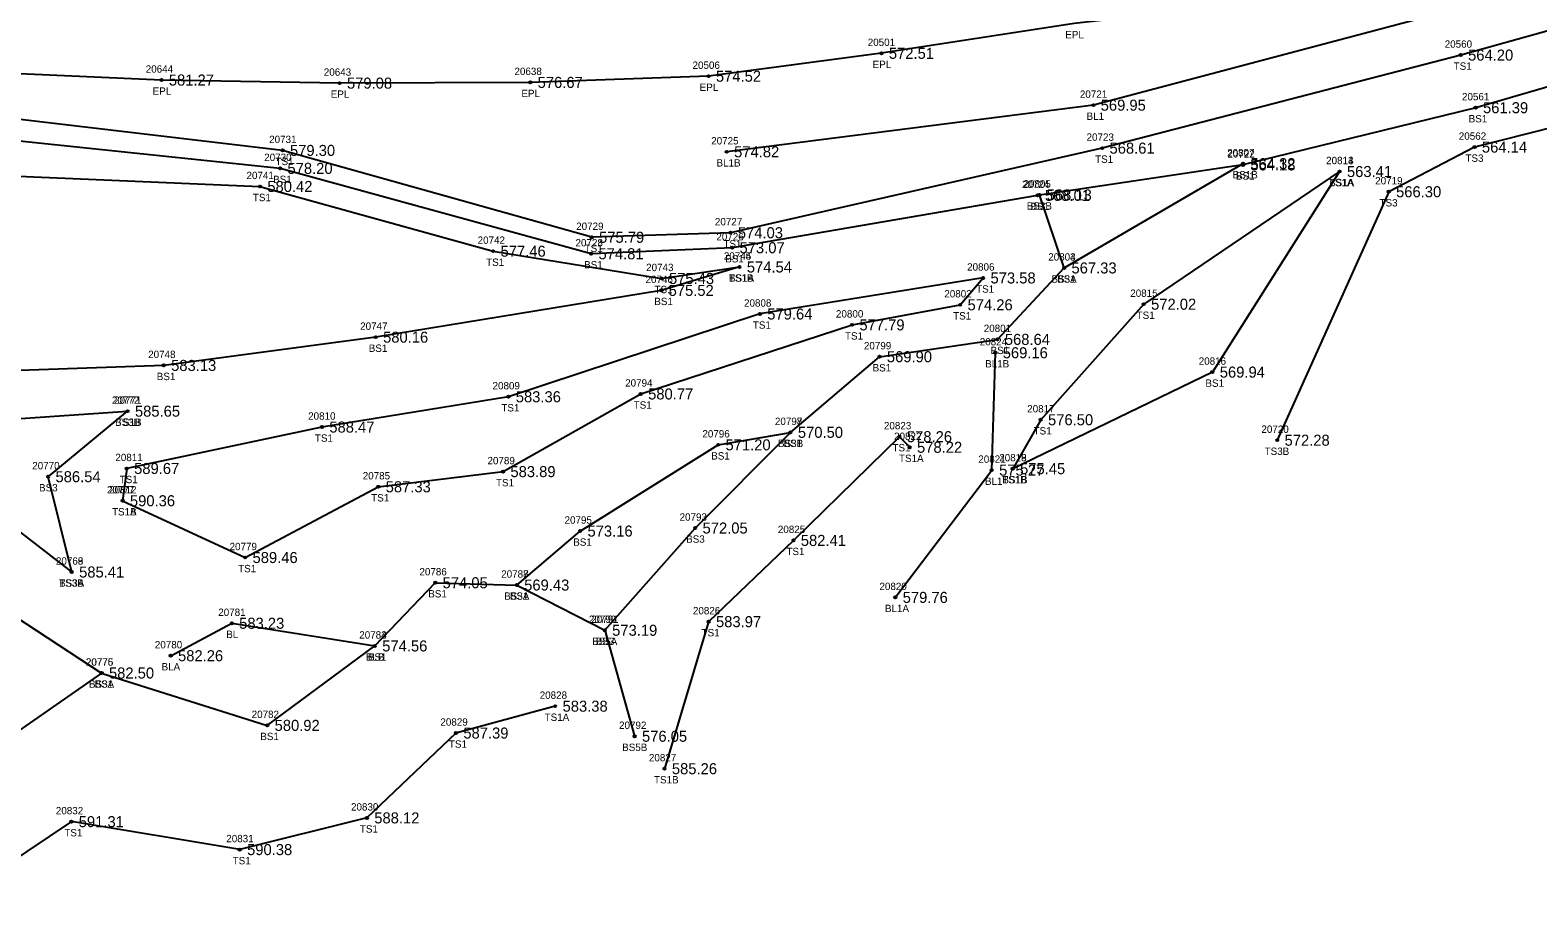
# Model space of a CAD drawing. Extents: x 1540443 to 1541844, y 887157 to 888162.
# Drawn here: x 1540572.9 to 1540777.9, y 887433.6 to 887551.3 of the extents above; entities that cross this region are included whole.
import ezdxf

# ---------------------------------------------------------------- set-up
doc = ezdxf.new("R2010")
doc.units = 0
for name, color, linetype in [('RD_DTM_BkLn1', 7, 'Continuous'), ('RD_DTM_BkLn2', 7, 'Continuous'), ('RD_DTM_BkLn_txCode', 7, 'Continuous'), ('RD_EX_Road', 7, 'Continuous'), ('RD_EX_Road_txCode', 7, 'Continuous'), ('RD_EX_TX_Misc_ELEV', 7, 'Continuous'), ('RD_EX_TX_Road_ELEV', 7, 'Continuous'), ('RD_SMD_Locator', 7, 'Continuous')]:
    doc.layers.add(name, color=color, linetype=linetype)

msp = doc.modelspace()

# ---------------------------------------------------------------- linework, layer by layer
at = {"layer": 'RD_DTM_BkLn1'}
for points in [[(1540954.63, 887607.67), (1540911.91, 887595.52), (1540863.1, 887582.06), (1540814.48, 887567.51), (1540766.41, 887554.06), (1540717.46, 887541.1), (1540667.62, 887534.76)], [(1540690.54, 887474.18), (1540703.65, 887491.48), (1540704.14, 887507.44)], [(1540592.02, 887466.25), (1540600.33, 887470.66), (1540619.78, 887467.58)]]:
    msp.add_lwpolyline(points, dxfattribs=at)
at = {"layer": 'RD_DTM_BkLn2'}
for p, q in [((1540713.49, 887518.97), (1540710.12, 887528.9)), ((1540553.06, 887497.25), (1540578.57, 887477.63)), ((1540651.04, 887469.71), (1540655.1, 887455.3)), ((1540582.63, 887463.9), (1540559.13, 887447.58))]:
    msp.add_line(p, q, dxfattribs=at)
for points in [[(1540960.58, 887575.27), (1540958.57, 887598.03), (1540949.34, 887601.53), (1540912.42, 887588.35), (1540865.58, 887574.46), (1540822.62, 887563.37), (1540767.41, 887547.91), (1540718.66, 887535.26), (1540668.13, 887523.76), (1540649.26, 887523.14), (1540607.24, 887534.95), (1540564.64, 887539.95), (1540513.61, 887544.12), (1540463.72, 887552.73)], [(1540960.58, 887575.27), (1540955.45, 887594.2), (1540950.03, 887596.51), (1540913.42, 887584.06), (1540866.75, 887567.94), (1540825.46, 887557.08), (1540769.44, 887540.76), (1540737.8, 887532.98), (1540709.87, 887528.84), (1540668.36, 887521.72), (1540649.18, 887520.9), (1540606.9, 887532.51), (1540564.07, 887536.98), (1540513.03, 887541.52), (1540462.71, 887549.66)], [(1540900.6, 887567.53), (1540867.5, 887560.94), (1540827.24, 887552.46), (1540817.08, 887547.51), (1540769.29, 887535.4), (1540757.62, 887529.33), (1540742.46, 887495.55)], [(1540461.05, 887539.25), (1540511.05, 887534.75), (1540564.9, 887531.71), (1540604.16, 887530.05), (1540635.87, 887521.25), (1540658.77, 887517.54), (1540669.35, 887519.1)], [(1540457.25, 887532.15), (1540491.31, 887510.51), (1540538.24, 887496.06), (1540547.91, 887492.89), (1540564.9, 887475.48), (1540582.63, 887463.9), (1540605.15, 887456.78), (1540619.78, 887467.58), (1540627.99, 887476.17), (1540639.08, 887475.86), (1540647.69, 887483.2), (1540666.45, 887494.92), (1540676.29, 887496.62), (1540688.39, 887506.9), (1540704.43, 887509.26), (1540713.49, 887518.97), (1540737.81, 887533.15)], [(1540457.25, 887532.15), (1540498.35, 887514), (1540541.32, 887498.88), (1540553.06, 887497.25), (1540586.16, 887499.5)], [(1540750.94, 887532.08), (1540733.65, 887504.81), (1540706.5, 887491.68)], [(1540750.94, 887532.08), (1540724.31, 887514.04), (1540710.3, 887498.33), (1540706.5, 887491.68)], [(1540669.35, 887519.1), (1540658.72, 887515.92), (1540619.9, 887509.56), (1540591.08, 887505.72), (1540555.73, 887504.5), (1540519.67, 887515.23), (1540490.26, 887524.32)], [(1540585.48, 887487.32), (1540602.15, 887479.6), (1540620.25, 887489.22), (1540637.21, 887491.28), (1540655.93, 887501.84), (1540684.66, 887511.23), (1540699.36, 887513.96), (1540702.48, 887517.61), (1540672.13, 887512.71), (1540637.94, 887501.46), (1540612.59, 887497.34), (1540586.05, 887491.71), (1540585.48, 887487.32)], [(1540578.57, 887477.63), (1540575.36, 887490.59), (1540586.16, 887499.5)], [(1540639.08, 887475.86), (1540651.04, 887469.71), (1540663.33, 887483.61), (1540676.29, 887496.62)], [(1540692.49, 887494.59), (1540691.11, 887496.03), (1540676.69, 887481.93), (1540665.16, 887470.88), (1540659.16, 887450.89)], [(1540644.3, 887459.39), (1540630.81, 887455.74), (1540618.7, 887444.2), (1540601.41, 887439.89), (1540578.52, 887443.69), (1540563.45, 887433.6)]]:
    msp.add_lwpolyline(points, dxfattribs=at)
at = {"layer": 'RD_EX_Road'}
msp.add_lwpolyline([(1541128.99, 887664.81), (1541102.04, 887656.79), (1541055.37, 887642.78), (1541004.6, 887628.06), (1540958.93, 887614.62), (1540910.77, 887599.96), (1540863.12, 887586.35), (1540837, 887578.35), (1540814.37, 887572.63), (1540785.6, 887565.57), (1540765.56, 887561), (1540743.15, 887555.32), (1540714.84, 887552.19), (1540688.66, 887548.15), (1540665.15, 887545.04), (1540640.91, 887544.2), (1540614.99, 887544.1), (1540590.77, 887544.52), (1540565.35, 887545.64), (1540542.9, 887547.56), (1540513.68, 887550.75), (1540490.5, 887554.02), (1540464.65, 887559.04)], dxfattribs=at)
at = {"layer": 'RD_SMD_Locator'}
for centre in [(1540688.66, 887548.15), (1540767.41, 887547.91), (1540665.15, 887545.04), (1540590.77, 887544.52), (1540614.99, 887544.1), (1540640.91, 887544.2), (1540717.46, 887541.1), (1540769.44, 887540.76), (1540607.24, 887534.95), (1540667.62, 887534.76), (1540718.66, 887535.26), (1540769.29, 887535.4), (1540737.8, 887532.98), (1540737.81, 887533.15), (1540606.9, 887532.51), (1540750.94, 887532.08), (1540750.94, 887532.08), (1540604.16, 887530.05), (1540709.87, 887528.84), (1540710.12, 887528.9), (1540757.62, 887529.33), (1540649.26, 887523.14), (1540668.13, 887523.76), (1540635.87, 887521.25), (1540649.18, 887520.9), (1540668.36, 887521.72), (1540669.35, 887519.1), (1540669.35, 887519.1), (1540713.49, 887518.97), (1540713.49, 887518.97), (1540658.77, 887517.54), (1540702.48, 887517.61), (1540658.72, 887515.92), (1540672.13, 887512.71), (1540699.36, 887513.96), (1540724.31, 887514.04), (1540684.66, 887511.23), (1540619.9, 887509.56), (1540704.43, 887509.26), (1540688.39, 887506.9), (1540704.14, 887507.44), (1540591.08, 887505.72), (1540733.65, 887504.81), (1540655.93, 887501.84), (1540637.94, 887501.46), (1540586.16, 887499.5), (1540586.16, 887499.5), (1540710.3, 887498.33), (1540612.59, 887497.34), (1540676.29, 887496.62), (1540676.29, 887496.62), (1540691.11, 887496.03), (1540666.45, 887494.92), (1540692.49, 887494.59), (1540742.46, 887495.55), (1540586.05, 887491.71), (1540706.5, 887491.68), (1540706.5, 887491.68), (1540575.36, 887490.59), (1540637.21, 887491.28), (1540703.65, 887491.48), (1540620.25, 887489.22), (1540585.48, 887487.32), (1540585.48, 887487.32), (1540663.33, 887483.61), (1540647.69, 887483.2), (1540676.69, 887481.93), (1540602.15, 887479.6), (1540578.57, 887477.63), (1540578.57, 887477.63), (1540627.99, 887476.17), (1540639.08, 887475.86), (1540639.08, 887475.86), (1540690.54, 887474.18), (1540600.33, 887470.66), (1540651.04, 887469.71), (1540651.04, 887469.71), (1540665.16, 887470.88), (1540619.78, 887467.58), (1540619.78, 887467.58), (1540592.02, 887466.25), (1540582.63, 887463.9), (1540582.63, 887463.9), (1540644.3, 887459.39), (1540605.15, 887456.78), (1540630.81, 887455.74), (1540655.1, 887455.3), (1540659.16, 887450.89), (1540578.52, 887443.69), (1540618.7, 887444.2), (1540601.41, 887439.89)]:
    msp.add_circle(centre, 0.15, dxfattribs=at)

# ---------------------------------------------------------------- texts
at = {"layer": 'RD_DTM_BkLn_txCode'}
for s, p in [('20560', (1540765.23, 887548.91)), ('TS1', (1540766.45, 887545.91)), ('20721', (1540715.63, 887542.1)), ('20561', (1540767.58, 887541.76)), ('BL1', (1540716.54, 887539.1)), ('BS1', (1540768.49, 887538.76)), ('20731', (1540605.41, 887535.95)), ('20725', (1540665.51, 887535.76)), ('20723', (1540716.54, 887536.26)), ('20562', (1540767.15, 887536.4)), ('20807', (1540735.65, 887534.15)), ('20722', (1540735.68, 887533.98)), ('20730', (1540604.74, 887533.51)), ('TS1', (1540606.28, 887532.95)), ('BL1B', (1540666.23, 887532.76)), ('TS1', (1540717.7, 887533.26)), ('20813', (1540749.11, 887533.08)), ('20814', (1540749.11, 887533.08)), ('TS3', (1540768.05, 887533.4)), ('20741', (1540602.33, 887531.05)), ('BS1', (1540605.95, 887530.51)), ('20724', (1540707.76, 887529.84)), ('20805', (1540707.96, 887529.9)), ('BS1B', (1540736.39, 887531.15)), ('BS1', (1540736.85, 887530.98)), ('TS1A', (1540749.49, 887530.08)), ('BS1A', (1540749.51, 887530.08)), ('20719', (1540755.78, 887530.33)), ('TS1', (1540603.2, 887528.05)), ('BS3B', (1540708.41, 887526.9)), ('BS1', (1540708.93, 887526.84)), ('TS3', (1540756.37, 887527.33)), ('20729', (1540647.15, 887524.14)), ('20727', (1540666.01, 887524.76)), ('20742', (1540633.75, 887522.25)), ('20728', (1540647.06, 887521.9)), ('20726', (1540666.21, 887522.72)), ('TS1', (1540667.17, 887521.76)), ('TS1', (1540648.3, 887521.14)), ('20744', (1540667.23, 887520.1)), ('20745', (1540667.23, 887520.1)), ('BS1', (1540667.41, 887519.72)), ('20803', (1540711.33, 887519.97)), ('20804', (1540711.33, 887519.97)), ('TS1', (1540634.91, 887519.25)), ('BS1', (1540648.23, 887518.9)), ('20743', (1540656.66, 887518.54)), ('20806', (1540700.3, 887518.61)), ('20746', (1540656.58, 887516.92)), ('TS1', (1540657.81, 887515.54)), ('TS1B', (1540667.92, 887517.1)), ('BS1A', (1540667.92, 887517.1)), ('TS1', (1540701.52, 887515.61)), ('BS3A', (1540711.77, 887516.97)), ('BS1', (1540712.54, 887516.97)), ('BS1', (1540657.77, 887513.92)), ('20808', (1540669.97, 887513.71)), ('20802', (1540697.2, 887514.96)), ('20815', (1540722.48, 887515.04)), ('20800', (1540682.47, 887512.23)), ('TS1', (1540698.4, 887511.96)), ('TS1', (1540723.35, 887512.04)), ('20747', (1540617.78, 887510.56)), ('TS1', (1540671.17, 887510.71)), ('TS1', (1540683.7, 887509.23)), ('20801', (1540702.56, 887510.26)), ('BS1', (1540618.95, 887507.56)), ('20799', (1540686.27, 887507.9)), ('20824', (1540702.02, 887508.44)), ('BS1', (1540703.49, 887507.26)), ('20748', (1540588.96, 887506.72)), ('BL1B', (1540702.75, 887505.44)), ('20816', (1540731.79, 887505.81)), ('BS1', (1540590.13, 887503.72)), ('BS1', (1540687.45, 887504.9)), ('20809', (1540635.78, 887502.46)), ('20794', (1540653.81, 887502.84)), ('BS1', (1540732.7, 887502.81)), ('20772', (1540584.04, 887500.5)), ('20771', (1540584.32, 887500.5)), ('TS1', (1540636.98, 887499.46)), ('TS1', (1540654.97, 887499.84)), ('20817', (1540708.47, 887499.33)), ('BS3B', (1540584.46, 887497.5)), ('TS1B', (1540584.72, 887497.5)), ('20810', (1540610.71, 887498.34)), ('20797', (1540674.17, 887497.62)), ('20798', (1540674.17, 887497.62)), ('20823', (1540688.99, 887497.03)), ('TS1', (1540611.63, 887495.34)), ('20796', (1540664.31, 887495.92)), ('20822', (1540690.37, 887495.59)), ('TS1', (1540709.34, 887496.33)), ('20720', (1540740.31, 887496.55)), ('BS1', (1540665.51, 887492.92)), ('BS3B', (1540674.59, 887494.62)), ('BS1', (1540675.34, 887494.62)), ('TS1', (1540690.15, 887494.03)), ('TS3B', (1540740.75, 887493.55)), ('20770', (1540573.2, 887491.59)), ('20811', (1540584.5, 887492.71)), ('20789', (1540635.09, 887492.28)), ('TS1A', (1540691.04, 887492.59)), ('20821', (1540701.82, 887492.48)), ('20818', (1540704.67, 887492.68)), ('20819', (1540704.67, 887492.68)), ('TS1', (1540585.09, 887489.71)), ('20785', (1540618.13, 887490.22)), ('TS1', (1540636.25, 887489.28)), ('BL1', (1540702.73, 887489.48)), ('TS1B', (1540705.07, 887489.68)), ('BS1B', (1540705.09, 887489.68)), ('BS3', (1540574.13, 887488.59)), ('20777', (1540583.37, 887488.32)), ('20812', (1540583.65, 887488.32)), ('TS1', (1540619.29, 887487.22)), ('TS1A', (1540584.04, 887485.32)), ('TS1B', (1540584.05, 887485.32)), ('20793', (1540661.21, 887484.61)), ('20795', (1540645.57, 887484.2)), ('20825', (1540674.57, 887482.93)), ('20779', (1540600.03, 887480.6)), ('BS1', (1540646.75, 887481.2)), ('BS3', (1540662.1, 887481.61)), ('20768', (1540576.42, 887478.63)), ('20769', (1540576.42, 887478.63)), ('TS1', (1540675.73, 887479.93)), ('TS1', (1540601.19, 887477.6)), ('20786', (1540625.84, 887477.17)), ('20787', (1540636.96, 887476.86)), ('20788', (1540636.96, 887476.86)), ('TS3B', (1540576.85, 887475.63)), ('BS3A', (1540576.85, 887475.63)), ('20820', (1540688.38, 887475.18)), ('BS1', (1540627.04, 887474.17)), ('BS3A', (1540637.36, 887473.86)), ('BS1', (1540638.13, 887473.86)), ('20781', (1540598.49, 887471.66)), ('20790', (1540648.88, 887470.71)), ('20791', (1540649.2, 887470.71)), ('20826', (1540663.02, 887471.88)), ('BL1A', (1540689.13, 887472.18)), ('BL', (1540599.57, 887468.66)), ('20783', (1540617.66, 887468.58)), ('20784', (1540617.66, 887468.58)), ('TS1', (1540664.2, 887468.88)), ('20780', (1540589.87, 887467.25)), ('BS5A', (1540649.32, 887467.71)), ('BS3', (1540649.81, 887467.71)), ('20776', (1540580.48, 887464.9)), ('20775', (1540580.51, 887464.9)), ('BLA', (1540590.78, 887464.25)), ('BLB', (1540618.55, 887465.58)), ('BS1', (1540618.83, 887465.58)), ('BS3A', (1540580.91, 887461.9)), ('BS1', (1540581.68, 887461.9)), ('20828', (1540642.19, 887460.39)), ('20782', (1540603.03, 887457.78)), ('20829', (1540628.69, 887456.74)), ('TS1A', (1540642.86, 887457.39)), ('20792', (1540652.98, 887456.3)), ('BS1', (1540604.2, 887454.78)), ('TS1', (1540629.85, 887453.74)), ('BS5B', (1540653.4, 887453.3)), ('20827', (1540657.04, 887451.89)), ('TS1B', (1540657.73, 887448.89)), ('20832', (1540576.41, 887444.69)), ('20830', (1540616.54, 887445.2)), ('TS1', (1540577.56, 887441.69)), ('TS1', (1540617.74, 887442.2)), ('20831', (1540599.58, 887440.89)), ('TS1', (1540600.45, 887437.89))]:
    msp.add_text(s, height=1, dxfattribs=at).set_placement(p)
at = {"layer": 'RD_EX_Road_txCode'}
for s, p in [('EPL', (1540713.64, 887550.19)), ('20501', (1540686.79, 887549.15)), ('20506', (1540662.97, 887546.04)), ('EPL', (1540687.46, 887546.15)), ('20644', (1540588.63, 887545.52)), ('20643', (1540612.84, 887545.1)), ('20638', (1540638.76, 887545.2)), ('EPL', (1540589.57, 887542.52)), ('EPL', (1540613.78, 887542.1)), ('EPL', (1540639.7, 887542.2)), ('EPL', (1540663.94, 887543.04))]:
    msp.add_text(s, height=1, dxfattribs=at).set_placement(p)
at = {"layer": 'RD_EX_TX_Misc_ELEV'}
for s, p in [('564.20', (1540768.41, 887547.16)), ('569.95', (1540718.46, 887540.35)), ('561.39', (1540770.44, 887540.01)), ('579.30', (1540608.24, 887534.2)), ('574.82', (1540668.62, 887534.01)), ('568.61', (1540719.66, 887534.51)), ('564.14', (1540770.29, 887534.65)), ('578.20', (1540607.9, 887531.76)), ('564.18', (1540738.8, 887532.23)), ('564.32', (1540738.81, 887532.4)), ('563.41', (1540751.94, 887531.33)), ('563.41', (1540751.94, 887531.33)), ('580.42', (1540605.16, 887529.3)), ('568.01', (1540710.87, 887528.09)), ('568.13', (1540711.12, 887528.15)), ('566.30', (1540758.62, 887528.58)), ('574.03', (1540669.13, 887523.01)), ('575.79', (1540650.26, 887522.39)), ('573.07', (1540669.36, 887520.97)), ('577.46', (1540636.87, 887520.5)), ('574.81', (1540650.18, 887520.15)), ('574.54', (1540670.35, 887518.35)), ('574.54', (1540670.35, 887518.35)), ('573.58', (1540703.48, 887516.86)), ('567.33', (1540714.49, 887518.22)), ('567.33', (1540714.49, 887518.22)), ('575.52', (1540659.72, 887515.17)), ('575.43', (1540659.77, 887516.79)), ('574.26', (1540700.36, 887513.21)), ('572.02', (1540725.31, 887513.29)), ('579.64', (1540673.13, 887511.96)), ('580.16', (1540620.9, 887508.81)), ('577.79', (1540685.66, 887510.48)), ('569.16', (1540705.14, 887506.69)), ('568.64', (1540705.43, 887508.51)), ('583.13', (1540592.08, 887504.97)), ('569.90', (1540689.39, 887506.15)), ('569.94', (1540734.65, 887504.06)), ('583.36', (1540638.94, 887500.71)), ('580.77', (1540656.93, 887501.09)), ('585.65', (1540587.16, 887498.75)), ('585.65', (1540587.16, 887498.75)), ('588.47', (1540613.59, 887496.59)), ('576.50', (1540711.3, 887497.58)), ('570.50', (1540677.29, 887495.87)), ('570.50', (1540677.29, 887495.87)), ('578.26', (1540692.11, 887495.28)), ('572.28', (1540743.46, 887494.8)), ('571.20', (1540667.45, 887494.17)), ('578.22', (1540693.49, 887493.84)), ('589.67', (1540587.05, 887490.96)), ('583.89', (1540638.21, 887490.53)), ('575.27', (1540704.65, 887490.73)), ('575.45', (1540707.5, 887490.93)), ('575.45', (1540707.5, 887490.93)), ('586.54', (1540576.36, 887489.84)), ('587.33', (1540621.25, 887488.47)), ('590.36', (1540586.48, 887486.57)), ('590.36', (1540586.48, 887486.57)), ('573.16', (1540648.69, 887482.45)), ('572.05', (1540664.33, 887482.86)), ('582.41', (1540677.69, 887481.18)), ('589.46', (1540603.15, 887478.85)), ('585.41', (1540579.57, 887476.88)), ('585.41', (1540579.57, 887476.88)), ('574.05', (1540628.99, 887475.42)), ('569.43', (1540640.08, 887475.11)), ('569.43', (1540640.08, 887475.11)), ('579.76', (1540691.54, 887473.43)), ('583.23', (1540601.33, 887469.91)), ('583.97', (1540666.16, 887470.13)), ('573.19', (1540652.04, 887468.96)), ('573.19', (1540652.04, 887468.96)), ('574.56', (1540620.78, 887466.83)), ('574.56', (1540620.78, 887466.83)), ('582.26', (1540593.02, 887465.5)), ('582.50', (1540583.63, 887463.15)), ('582.50', (1540583.63, 887463.15)), ('583.38', (1540645.3, 887458.64)), ('580.92', (1540606.15, 887456.03)), ('587.39', (1540631.81, 887454.99)), ('576.05', (1540656.1, 887454.55)), ('585.26', (1540660.16, 887450.14)), ('588.12', (1540619.7, 887443.45)), ('591.31', (1540579.52, 887442.94)), ('590.38', (1540602.41, 887439.14))]:
    msp.add_text(s, height=1.5, dxfattribs=at).set_placement(p)
at = {"layer": 'RD_EX_TX_Road_ELEV'}
for s, p in [('572.51', (1540689.66, 887547.4)), ('581.27', (1540591.77, 887543.77)), ('574.52', (1540666.15, 887544.29)), ('579.08', (1540615.99, 887543.35)), ('576.67', (1540641.91, 887543.45))]:
    msp.add_text(s, height=1.5, dxfattribs=at).set_placement(p)

doc.saveas('drawing.dxf')
